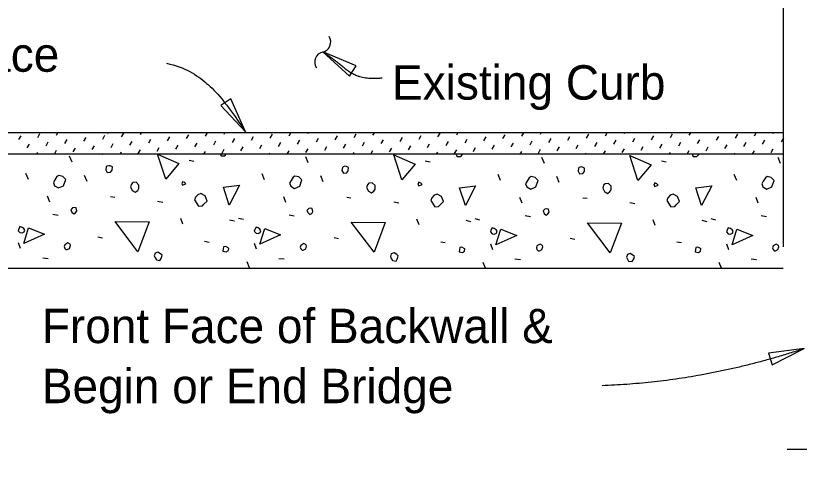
# Model space of a CAD drawing. Extents: x 21526.6 to 21595.9, y 56114.9 to 56157.2.
# Drawn here: x 21531.109 to 21535.704, y 56132.489 to 56135.147 of the extents above; entities that cross this region are included whole.
import ezdxf

# ---------------------------------------------------------------- set-up
doc = ezdxf.new("R2010")
doc.units = 0
for name, color, linetype in [('AdhocPoint_dp', 7, 'Continuous'), ('Border', 7, 'Continuous'), ('Patterning', 7, 'Continuous'), ('PlotBorder_dp', 7, 'Continuous')]:
    doc.layers.add(name, color=color, linetype=linetype)

msp = doc.modelspace()

# ---------------------------------------------------------------- linework, layer by layer
at = {"layer": 'AdhocPoint_dp'}
for p, q in [((21535.6096, 56135.2099), (21535.6096, 56133.7934)), ((21535.6096, 56134.46), (21527.2426, 56134.46)), ((21535.6096, 56134.335), (21527.2426, 56134.335)), ((21527.2426, 56133.6684), (21535.6096, 56133.6684))]:
    msp.add_line(p, q, dxfattribs=at)
at = {"layer": 'Patterning'}
for p, q in [((21531.1274, 56134.4209), (21531.1404, 56134.4433)), ((21531.238, 56134.4338), (21531.251, 56134.4562)), ((21531.3487, 56134.4468), (21531.3563, 56134.46)), ((21531.4593, 56134.4598), (21531.4595, 56134.46)), ((21531.5081, 56134.4109), (21531.5211, 56134.4333)), ((21531.6188, 56134.4239), (21531.6317, 56134.4463)), ((21531.6499, 56134.4561), (21531.6501, 56134.4564)), ((21531.7294, 56134.4369), (21531.7424, 56134.4592)), ((21531.84, 56134.4498), (21531.846, 56134.46)), ((21531.8889, 56134.401), (21531.9018, 56134.4234)), ((21531.9995, 56134.4139), (21532.0125, 56134.4363)), ((21532.1101, 56134.4269), (21532.1231, 56134.4493)), ((21532.2208, 56134.4399), (21532.2324, 56134.46)), ((21532.3314, 56134.4528), (21532.3356, 56134.46)), ((21532.3802, 56134.404), (21532.3932, 56134.4264)), ((21532.4909, 56134.417), (21532.5038, 56134.4394)), ((21532.6015, 56134.4299), (21532.6145, 56134.4523)), ((21532.7121, 56134.4429), (21532.7221, 56134.46)), ((21532.8228, 56134.4559), (21532.8252, 56134.46)), ((21532.8716, 56134.407), (21532.8846, 56134.4294)), ((21532.9822, 56134.42), (21532.9952, 56134.4424)), ((21533.0929, 56134.433), (21533.1058, 56134.4553)), ((21533.2035, 56134.4459), (21533.2117, 56134.46)), ((21533.3141, 56134.4589), (21533.3148, 56134.46)), ((21533.363, 56134.41), (21533.3759, 56134.4324)), ((21533.4736, 56134.423), (21533.4866, 56134.4454)), ((21533.5842, 56134.436), (21533.5972, 56134.4584)), ((21533.6949, 56134.4489), (21533.7013, 56134.46)), ((21533.7439, 56134.401), (21533.7569, 56134.4234)), ((21533.8545, 56134.4139), (21533.8675, 56134.4363)), ((21533.9652, 56134.4269), (21533.9781, 56134.4493)), ((21534.0758, 56134.4399), (21534.0875, 56134.46)), ((21534.1864, 56134.4528), (21534.1906, 56134.46)), ((21534.2353, 56134.404), (21534.2482, 56134.4264)), ((21534.3459, 56134.417), (21534.3589, 56134.4394)), ((21534.4565, 56134.4299), (21534.4695, 56134.4523)), ((21534.5672, 56134.4429), (21534.5771, 56134.46)), ((21534.6778, 56134.4559), (21534.6802, 56134.46)), ((21534.7266, 56134.407), (21534.7396, 56134.4294)), ((21534.8373, 56134.42), (21534.8502, 56134.4424)), ((21534.9479, 56134.433), (21534.9609, 56134.4553)), ((21535.0585, 56134.4459), (21535.0667, 56134.46)), ((21535.2185, 56134.417), (21535.2315, 56134.4394)), ((21535.3292, 56134.4299), (21535.3421, 56134.4523)), ((21535.4398, 56134.4429), (21535.4497, 56134.46)), ((21535.5504, 56134.4559), (21535.5529, 56134.46)), ((21535.5993, 56134.407), (21535.6122, 56134.4294)), ((21531.1762, 56134.372), (21531.1892, 56134.3944)), ((21531.2869, 56134.385), (21531.2998, 56134.4074)), ((21531.3975, 56134.398), (21531.4105, 56134.4204)), ((21531.557, 56134.3621), (21531.5699, 56134.3845)), ((21531.6676, 56134.3751), (21531.6806, 56134.3975)), ((21531.7782, 56134.388), (21531.7912, 56134.4104)), ((21532.0483, 56134.3651), (21532.0613, 56134.3875)), ((21532.159, 56134.3781), (21532.1719, 56134.4005)), ((21532.2696, 56134.391), (21532.2826, 56134.4134)), ((21532.4291, 56134.3552), (21532.442, 56134.3776)), ((21532.5397, 56134.3681), (21532.5527, 56134.3905)), ((21532.6503, 56134.3811), (21532.6633, 56134.4035)), ((21532.761, 56134.3941), (21532.7739, 56134.4165)), ((21532.9204, 56134.3582), (21532.9334, 56134.3806)), ((21533.0311, 56134.3712), (21533.044, 56134.3935)), ((21533.1417, 56134.3841), (21533.1547, 56134.4065)), ((21533.2523, 56134.3971), (21533.2653, 56134.4195)), ((21533.4118, 56134.3612), (21533.4248, 56134.3836)), ((21533.5224, 56134.3742), (21533.5354, 56134.3966)), ((21533.6331, 56134.3871), (21533.646, 56134.4095)), ((21533.9034, 56134.3651), (21533.9163, 56134.3875)), ((21534.014, 56134.3781), (21534.027, 56134.4005)), ((21534.1246, 56134.391), (21534.1376, 56134.4134)), ((21534.2841, 56134.3552), (21534.2971, 56134.3776)), ((21534.3947, 56134.3681), (21534.4077, 56134.3905)), ((21534.5054, 56134.3811), (21534.5183, 56134.4035)), ((21534.616, 56134.3941), (21534.629, 56134.4165)), ((21534.7755, 56134.3582), (21534.7884, 56134.3806)), ((21534.8861, 56134.3712), (21534.8991, 56134.3935)), ((21534.9967, 56134.3841), (21535.0097, 56134.4065)), ((21535.1074, 56134.3971), (21535.1203, 56134.4195)), ((21535.1568, 56134.3552), (21535.1697, 56134.3776)), ((21535.2674, 56134.3681), (21535.2803, 56134.3905)), ((21535.378, 56134.3811), (21535.391, 56134.4035)), ((21535.4886, 56134.3941), (21535.5016, 56134.4165)), ((21531.2319, 56134.335), (21531.238, 56134.3456)), ((21531.3357, 56134.3362), (21531.3487, 56134.3586)), ((21531.4463, 56134.3491), (21531.4593, 56134.3715)), ((21531.6184, 56134.335), (21531.6188, 56134.3357)), ((21531.7215, 56134.335), (21531.7294, 56134.3486)), ((21531.8271, 56134.3392), (21531.84, 56134.3616)), ((21531.9377, 56134.3522), (21531.9507, 56134.3745)), ((21532.108, 56134.335), (21532.1101, 56134.3387)), ((21532.2112, 56134.335), (21532.2208, 56134.3516)), ((21532.3184, 56134.3422), (21532.3314, 56134.3646)), ((21532.5977, 56134.335), (21532.6015, 56134.3417)), ((21532.7008, 56134.335), (21532.7121, 56134.3547)), ((21532.8098, 56134.3452), (21532.8228, 56134.3676)), ((21533.0873, 56134.335), (21533.0929, 56134.3447)), ((21533.1905, 56134.3353), (21533.2035, 56134.3577)), ((21533.3012, 56134.3482), (21533.3141, 56134.3706)), ((21533.5769, 56134.335), (21533.5842, 56134.3477)), ((21533.6821, 56134.3392), (21533.6951, 56134.3616)), ((21533.7925, 56134.3513), (21533.8055, 56134.3737)), ((21533.7927, 56134.3522), (21533.8057, 56134.3745)), ((21533.9631, 56134.335), (21533.9652, 56134.3387)), ((21534.0662, 56134.335), (21534.0758, 56134.3516)), ((21534.1735, 56134.3422), (21534.1864, 56134.3646)), ((21534.4527, 56134.335), (21534.4565, 56134.3417)), ((21534.5558, 56134.335), (21534.5672, 56134.3547)), ((21534.6648, 56134.3452), (21534.6778, 56134.3676)), ((21534.9423, 56134.335), (21534.9479, 56134.3447)), ((21535.0456, 56134.3353), (21535.0585, 56134.3577)), ((21535.3253, 56134.335), (21535.3292, 56134.3417)), ((21535.4285, 56134.335), (21535.4398, 56134.3547)), ((21535.5375, 56134.3452), (21535.5504, 56134.3676)), ((21531.4391, 56134.2884), (21531.425, 56134.3238)), ((21532.1255, 56134.3008), (21532.1538, 56134.2937)), ((21532.8238, 56134.2849), (21532.8097, 56134.3203)), ((21533.5102, 56134.2973), (21533.5385, 56134.2902)), ((21534.2085, 56134.2814), (21534.1943, 56134.3167)), ((21534.8945, 56134.2973), (21534.9228, 56134.2902)), ((21535.5928, 56134.2814), (21535.5786, 56134.3167)), ((21531.1828, 56134.1877), (21531.1687, 56134.223)), ((21531.5269, 56134.1759), (21531.5128, 56134.2113)), ((21532.5675, 56134.1841), (21532.5533, 56134.2195)), ((21532.9116, 56134.1724), (21532.8974, 56134.2077)), ((21533.9522, 56134.1806), (21533.938, 56134.216)), ((21534.2962, 56134.1689), (21534.2821, 56134.2042)), ((21535.3364, 56134.1806), (21535.3223, 56134.216)), ((21531.3083, 56134.0551), (21531.2959, 56134.0887)), ((21531.6648, 56134.0875), (21531.6895, 56134.084)), ((21531.9406, 56134.0593), (21531.9706, 56134.0539)), ((21532.693, 56134.0516), (21532.6806, 56134.0851)), ((21533.0495, 56134.084), (21533.0742, 56134.0805)), ((21533.3252, 56134.0557), (21533.3553, 56134.0504)), ((21534.0777, 56134.048), (21534.0653, 56134.0816)), ((21534.4341, 56134.0805), (21534.4589, 56134.0769)), ((21535.462, 56134.048), (21535.4496, 56134.0816)), ((21534.7099, 56134.0522), (21534.74, 56134.0469)), ((21531.3271, 56133.9832), (21531.3572, 56133.9779)), ((21532.7118, 56133.9797), (21532.7419, 56133.9744)), ((21534.0965, 56133.9762), (21534.1265, 56133.9709)), ((21535.4808, 56133.9762), (21535.5108, 56133.9709)), ((21532.089, 56133.9249), (21532.0767, 56133.9585)), ((21532.363, 56133.9514), (21532.3913, 56133.9443)), ((21532.4155, 56133.9614), (21532.4437, 56133.9543)), ((21533.4737, 56133.9214), (21533.4613, 56133.955)), ((21533.7477, 56133.9479), (21533.776, 56133.9408)), ((21533.8001, 56133.9579), (21533.8284, 56133.9508)), ((21534.8584, 56133.9178), (21534.846, 56133.9514)), ((21535.132, 56133.9479), (21535.1603, 56133.9408)), ((21535.1844, 56133.9579), (21535.2127, 56133.9508)), ((21531.5905, 56133.8507), (21531.6171, 56133.8454)), ((21532.2163, 56133.8259), (21532.2428, 56133.8206)), ((21532.9752, 56133.8471), (21533.0017, 56133.8418)), ((21534.3599, 56133.8436), (21534.3864, 56133.8383)), ((21531.1368, 56133.7823), (21531.1245, 56133.8159)), ((21532.5215, 56133.7788), (21532.5091, 56133.8124)), ((21533.601, 56133.8224), (21533.6275, 56133.8171)), ((21533.9062, 56133.7753), (21533.8938, 56133.8089)), ((21534.9853, 56133.8224), (21535.0118, 56133.8171)), ((21535.2905, 56133.7753), (21535.2781, 56133.8089)), ((21531.267, 56133.7287), (21531.2989, 56133.7251)), ((21532.4791, 56133.6692), (21532.465, 56133.7046)), ((21532.6517, 56133.7251), (21532.6835, 56133.7216)), ((21533.8627, 56133.6684), (21533.8496, 56133.701)), ((21534.0364, 56133.7216), (21534.0682, 56133.7181)), ((21535.247, 56133.6684), (21535.2339, 56133.701)), ((21535.4207, 56133.7216), (21535.4525, 56133.7181))]:
    msp.add_line(p, q, dxfattribs=at)
for points in [[(21531.9883, 56134.1883), (21531.9406, 56134.335), (21532.0661, 56134.2802), (21531.9883, 56134.1883)], [(21532.3089, 56134.335), (21532.3129, 56134.3256), (21532.3094, 56134.3291)], [(21532.3129, 56134.3256), (21532.3341, 56134.3256), (21532.3436, 56134.335)], [(21533.373, 56134.1848), (21533.3252, 56134.3315), (21533.4507, 56134.2767), (21533.373, 56134.1848)], [(21533.6927, 56134.335), (21533.6923, 56134.3344), (21533.6976, 56134.322), (21533.6941, 56134.3256)], [(21533.6976, 56134.322), (21533.7188, 56134.322), (21533.7294, 56134.3326), (21533.7288, 56134.335)], [(21535.077, 56134.335), (21535.0766, 56134.3344), (21535.0819, 56134.322), (21535.0784, 56134.3256)], [(21535.0819, 56134.322), (21535.1031, 56134.322), (21535.1137, 56134.3326), (21535.1131, 56134.335)], [(21534.7576, 56134.1812), (21534.7099, 56134.328), (21534.8354, 56134.2731), (21534.7576, 56134.1812)], [(21531.6365, 56134.2431), (21531.6453, 56134.2272), (21531.6648, 56134.229), (21531.6736, 56134.2413), (21531.6754, 56134.2608), (21531.663, 56134.2661), (21531.6542, 56134.2678), (21531.6436, 56134.2643), (21531.64, 56134.2608), (21531.6365, 56134.2431)], [(21533.0212, 56134.2396), (21533.03, 56134.2237), (21533.0495, 56134.2254), (21533.0583, 56134.2378), (21533.0601, 56134.2572), (21533.0477, 56134.2625), (21533.0389, 56134.2643), (21533.0282, 56134.2608), (21533.0247, 56134.2572), (21533.0212, 56134.2396)], [(21534.4059, 56134.236), (21534.4147, 56134.2201), (21534.4341, 56134.2219), (21534.443, 56134.2343), (21534.4447, 56134.2537), (21534.4324, 56134.259), (21534.4235, 56134.2608), (21534.4129, 56134.2572), (21534.4094, 56134.2537), (21534.4059, 56134.236)], [(21531.3366, 56134.1505), (21531.3596, 56134.1382), (21531.3896, 56134.1505), (21531.402, 56134.1877), (21531.3843, 56134.2053), (21531.3614, 56134.2107), (21531.3507, 56134.2036), (21531.3384, 56134.1841), (21531.3295, 56134.1682), (21531.3366, 56134.1505)], [(21532.7213, 56134.147), (21532.7443, 56134.1346), (21532.7743, 56134.147), (21532.7867, 56134.1841), (21532.769, 56134.2018), (21532.746, 56134.2071), (21532.7354, 56134.2), (21532.723, 56134.1806), (21532.7142, 56134.1647), (21532.7213, 56134.147)], [(21534.106, 56134.1435), (21534.1289, 56134.1311), (21534.159, 56134.1435), (21534.1714, 56134.1806), (21534.1537, 56134.1983), (21534.1307, 56134.2036), (21534.1201, 56134.1965), (21534.1077, 56134.1771), (21534.0989, 56134.1612), (21534.106, 56134.1435)], [(21535.4902, 56134.1435), (21535.5132, 56134.1311), (21535.5433, 56134.1435), (21535.5557, 56134.1806), (21535.538, 56134.1983), (21535.515, 56134.2036), (21535.5044, 56134.1965), (21535.492, 56134.1771), (21535.4832, 56134.1612), (21535.4902, 56134.1435)], [(21531.7815, 56134.1441), (21531.7921, 56134.1229), (21531.8097, 56134.1123), (21531.8239, 56134.1229), (21531.831, 56134.1335), (21531.831, 56134.1547), (21531.815, 56134.1706), (21531.7956, 56134.1689), (21531.7868, 56134.16), (21531.7815, 56134.1441)], [(21532.0873, 56134.1529), (21532.1067, 56134.1618), (21532.0997, 56134.1689), (21532.0873, 56134.1742), (21532.082, 56134.1618), (21532.0873, 56134.1529)], [(21532.3607, 56134.0374), (21532.3271, 56134.1417), (21532.4208, 56134.1541), (21532.3607, 56134.0374)], [(21533.1661, 56134.1406), (21533.1767, 56134.1194), (21533.1944, 56134.1087), (21533.2086, 56134.1194), (21533.2156, 56134.13), (21533.2156, 56134.1512), (21533.1997, 56134.1671), (21533.1803, 56134.1653), (21533.1714, 56134.1565), (21533.1661, 56134.1406)], [(21533.472, 56134.1494), (21533.4914, 56134.1582), (21533.4843, 56134.1653), (21533.472, 56134.1706), (21533.4667, 56134.1582), (21533.472, 56134.1494)], [(21533.7453, 56134.0339), (21533.7117, 56134.1382), (21533.8054, 56134.1505), (21533.7453, 56134.0339)], [(21534.5508, 56134.137), (21534.5614, 56134.1158), (21534.5791, 56134.1052), (21534.5932, 56134.1158), (21534.6003, 56134.1264), (21534.6003, 56134.1476), (21534.5844, 56134.1635), (21534.5649, 56134.1618), (21534.5561, 56134.1529), (21534.5508, 56134.137)], [(21534.8566, 56134.1459), (21534.8761, 56134.1547), (21534.869, 56134.1618), (21534.8566, 56134.1671), (21534.8513, 56134.1547), (21534.8566, 56134.1459)], [(21535.1296, 56134.0339), (21535.096, 56134.1382), (21535.1897, 56134.1505), (21535.1296, 56134.0339)], [(21532.158, 56134.0681), (21532.181, 56134.031), (21532.2039, 56134.0327), (21532.2128, 56134.0416), (21532.2322, 56134.061), (21532.2199, 56134.0911), (21532.1951, 56134.1052), (21532.1774, 56134.0981), (21532.1633, 56134.084), (21532.158, 56134.0681)], [(21533.5427, 56134.0646), (21533.5656, 56134.0274), (21533.5886, 56134.0292), (21533.5975, 56134.038), (21533.6169, 56134.0575), (21533.6045, 56134.0875), (21533.5798, 56134.1017), (21533.5621, 56134.0946), (21533.548, 56134.0805), (21533.5427, 56134.0646)], [(21534.927, 56134.0646), (21534.9499, 56134.0274), (21534.9729, 56134.0292), (21534.9818, 56134.038), (21535.0012, 56134.0575), (21534.9888, 56134.0875), (21534.9641, 56134.1017), (21534.9464, 56134.0946), (21534.9323, 56134.0805), (21534.927, 56134.0646)], [(21531.4385, 56133.9956), (21531.4491, 56133.985), (21531.4597, 56133.9921), (21531.4668, 56134.0027), (21531.4633, 56134.0204), (21531.4544, 56134.0221), (21531.442, 56134.0204), (21531.4314, 56134.0098), (21531.4385, 56133.9956)], [(21532.8232, 56133.9921), (21532.8338, 56133.9815), (21532.8444, 56133.9885), (21532.8515, 56133.9991), (21532.8479, 56134.0168), (21532.8391, 56134.0186), (21532.8267, 56134.0168), (21532.8161, 56134.0062), (21532.8232, 56133.9921)], [(21534.2079, 56133.9885), (21534.2185, 56133.9779), (21534.2291, 56133.985), (21534.2361, 56133.9956), (21534.2326, 56134.0133), (21534.2238, 56134.0151), (21534.2114, 56134.0133), (21534.2008, 56134.0027), (21534.2079, 56133.9885)], [(21531.8256, 56133.764), (21531.6913, 56133.9408), (21531.8911, 56133.939), (21531.8256, 56133.764)], [(21533.2103, 56133.7605), (21533.076, 56133.9373), (21533.2757, 56133.9355), (21533.2103, 56133.7605)], [(21534.595, 56133.757), (21534.4607, 56133.9337), (21534.6604, 56133.932), (21534.595, 56133.757)], [(21531.1333, 56133.8765), (21531.1457, 56133.8748), (21531.1581, 56133.8801), (21531.1616, 56133.8907), (21531.1563, 56133.8995), (21531.1457, 56133.9066), (21531.1333, 56133.9119), (21531.1262, 56133.8978), (21531.1227, 56133.8872), (21531.1333, 56133.8765)], [(21531.1557, 56133.8118), (21531.1839, 56133.9037), (21531.2776, 56133.8666), (21531.1557, 56133.8118)], [(21532.518, 56133.873), (21532.5304, 56133.8712), (21532.5427, 56133.8765), (21532.5463, 56133.8872), (21532.541, 56133.896), (21532.5304, 56133.9031), (21532.518, 56133.9084), (21532.5109, 56133.8942), (21532.5074, 56133.8836), (21532.518, 56133.873)], [(21532.5403, 56133.8082), (21532.5686, 56133.9002), (21532.6623, 56133.863), (21532.5403, 56133.8082)], [(21533.9027, 56133.8695), (21533.915, 56133.8677), (21533.9274, 56133.873), (21533.9309, 56133.8836), (21533.9256, 56133.8925), (21533.915, 56133.8995), (21533.9027, 56133.9048), (21533.8956, 56133.8907), (21533.8921, 56133.8801), (21533.9027, 56133.8695)], [(21533.925, 56133.8047), (21533.9533, 56133.8966), (21534.047, 56133.8595), (21533.925, 56133.8047)], [(21535.2869, 56133.8695), (21535.2993, 56133.8677), (21535.3117, 56133.873), (21535.3152, 56133.8836), (21535.3099, 56133.8925), (21535.2993, 56133.8995), (21535.2869, 56133.9048), (21535.2799, 56133.8907), (21535.2763, 56133.8801), (21535.2869, 56133.8695)], [(21535.3093, 56133.8047), (21535.3376, 56133.8966), (21535.4313, 56133.8595), (21535.3093, 56133.8047)], [(21531.4032, 56133.7764), (21531.4102, 56133.7764), (21531.4244, 56133.7835), (21531.4297, 56133.7994), (21531.4279, 56133.8082), (21531.4138, 56133.8153), (21531.3961, 56133.8047), (21531.3925, 56133.7941), (21531.3961, 56133.7835), (21531.4032, 56133.7764)], [(21532.3242, 56133.7676), (21532.3436, 56133.7623), (21532.356, 56133.7711), (21532.3577, 56133.7835), (21532.3542, 56133.787), (21532.3401, 56133.7941), (21532.3277, 56133.7923), (21532.3259, 56133.7799), (21532.3242, 56133.7676)], [(21532.7878, 56133.7729), (21532.7949, 56133.7729), (21532.809, 56133.7799), (21532.8143, 56133.7959), (21532.8126, 56133.8047), (21532.7984, 56133.8118), (21532.7808, 56133.8012), (21532.7772, 56133.7905), (21532.7808, 56133.7799), (21532.7878, 56133.7729)], [(21533.7088, 56133.764), (21533.7283, 56133.7587), (21533.7407, 56133.7676), (21533.7424, 56133.7799), (21533.7389, 56133.7835), (21533.7247, 56133.7905), (21533.7124, 56133.7888), (21533.7106, 56133.7764), (21533.7088, 56133.764)], [(21534.1725, 56133.7693), (21534.1796, 56133.7693), (21534.1937, 56133.7764), (21534.199, 56133.7923), (21534.1973, 56133.8012), (21534.1831, 56133.8082), (21534.1654, 56133.7976), (21534.1619, 56133.787), (21534.1654, 56133.7764), (21534.1725, 56133.7693)], [(21535.0931, 56133.764), (21535.1126, 56133.7587), (21535.1249, 56133.7676), (21535.1267, 56133.7799), (21535.1232, 56133.7835), (21535.109, 56133.7905), (21535.0967, 56133.7888), (21535.0949, 56133.7764), (21535.0931, 56133.764)], [(21535.5568, 56133.7693), (21535.5639, 56133.7693), (21535.578, 56133.7764), (21535.5833, 56133.7923), (21535.5815, 56133.8012), (21535.5674, 56133.8082), (21535.5497, 56133.7976), (21535.5462, 56133.787), (21535.5497, 56133.7764), (21535.5568, 56133.7693)], [(21531.9246, 56133.7322), (21531.9335, 56133.7163), (21531.9547, 56133.7128), (21531.9635, 56133.7287), (21531.9671, 56133.7428), (21531.9582, 56133.7517), (21531.9423, 56133.7605), (21531.9264, 56133.7552), (21531.9211, 56133.7393), (21531.9246, 56133.7322)], [(21533.3093, 56133.7287), (21533.3182, 56133.7128), (21533.3394, 56133.7092), (21533.3482, 56133.7251), (21533.3517, 56133.7393), (21533.3429, 56133.7481), (21533.327, 56133.757), (21533.3111, 56133.7517), (21533.3058, 56133.7357), (21533.3093, 56133.7287)], [(21534.694, 56133.7251), (21534.7028, 56133.7092), (21534.724, 56133.7057), (21534.7329, 56133.7216), (21534.7364, 56133.7357), (21534.7276, 56133.7446), (21534.7117, 56133.7534), (21534.6958, 56133.7481), (21534.6905, 56133.7322), (21534.694, 56133.7251)]]:
    msp.add_lwpolyline(points, dxfattribs=at)
at = {"layer": 'PlotBorder_dp'}
for points in [[(21532.9092, 56134.934), (21533.0667, 56134.7933), (21533.1043, 56134.8531)], [(21532.4557, 56134.4666), (21532.3692, 56134.6593), (21532.3106, 56134.6201)], [(21535.7321, 56133.1961), (21535.5227, 56133.1687), (21535.5434, 56133.1013)]]:
    msp.add_lwpolyline(points, close=True, dxfattribs=at)
msp.add_lwpolyline([(21536.8321, 56132.6054), (21536.356, 56132.6054), (21536.356, 56132.4891), (21536.2566, 56132.7141), (21536.2566, 56132.6054), (21535.6321, 56132.6054)], dxfattribs=at)
for centre, start, end in [((21532.8964, 56134.9917), 282.0365, 33.7637), ((21532.9213, 56134.8751), 102.0365, 213.7637)]:
    msp.add_arc(centre, 0.0596, start, end, dxfattribs=at)
for points, degree in [([(21533.2579, 56134.7814), (21533.1271, 56134.7638), (21532.9641, 56134.8995), (21532.9092, 56134.934)], 2), ([(21531.9932, 56134.8676), (21532.1019, 56134.8461), (21532.2376, 56134.7542), (21532.335, 56134.647), (21532.4557, 56134.4666)], 3), ([(21535.7321, 56133.1961), (21535.1397, 56133.0001), (21534.5473, 56132.979)], 2)]:
    msp.add_open_spline(points, degree=degree, dxfattribs=at)

# ---------------------------------------------------------------- texts
at = {"layer": 'Border'}
for s, p in [('Final Riding Surface', (21528.9369, 56134.8183)), ('Existing Curb', (21533.3155, 56134.6548))]:
    msp.add_text(s, height=0.2016, dxfattribs=at).set_placement(p)
at = {"layer": 'PlotBorder_dp'}
for s, p in [('Front Face of Backwall &', (21531.262, 56133.2284)), ('Begin or End Bridge', (21531.262, 56132.8764))]:
    msp.add_text(s, height=0.2016, dxfattribs=at).set_placement(p)

doc.saveas('drawing.dxf')
